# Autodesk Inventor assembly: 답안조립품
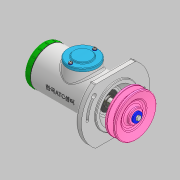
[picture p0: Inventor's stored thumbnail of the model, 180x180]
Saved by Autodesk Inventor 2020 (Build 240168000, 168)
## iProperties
Created: 2022-05
Part Number: 답안조립품
Document SubType Name: Assembly
Designer: User
Author: User
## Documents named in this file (22)
- C:\Users\User\Desktop\720506V1035\답안조립품.iam
- C:\Users\User\Desktop\720506V1035\본체.ipt
- C:\Users\User\Desktop\720506V1035\V-벨트풀리.ipt
- C:\Users\User\Desktop\720506V1035\개스킷.ipt
- C:\Users\User\Desktop\720506V1035\너트 M10.ipt
- C:\Users\User\Desktop\720506V1035\멈춤나사 M3.ipt
- C:\Users\User\Desktop\720506V1035\멈춤링 15 x 1.ipt
- C:\Users\User\Desktop\720506V1035\멈춤링 35 x 1.6.ipt
- C:\Users\User\Desktop\720506V1035\베어링 6202.ipt
- C:\Users\User\Desktop\720506V1035\볼트 M4 x 10.ipt
- C:\Users\User\Desktop\720506V1035\부시1.ipt
- C:\Users\User\Desktop\720506V1035\부시2.ipt
- C:\Users\User\Desktop\720506V1035\사이드 커버.ipt
- 사이드 커버.ipt
- C:\Users\User\Desktop\720506V1035\십자볼트 M3 x 10.ipt
- C:\Users\User\Desktop\720506V1035\오일 실 15 x 30 x 7.ipt
- C:\Users\User\Desktop\720506V1035\와셔 3 x 6.ipt
- C:\Users\User\Desktop\720506V1035\와셔 4 x 16.ipt
- C:\Users\User\Desktop\720506V1035\와셔 10 x 21.ipt
- C:\Users\User\Desktop\720506V1035\축.ipt
- C:\Users\User\Desktop\720506V1035\키 4 x 4.ipt
- C:\Users\User\Desktop\720506V1035\탑 커버.ipt
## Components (3 placed, 3 different names)
1. V-벨트풀리:1
2. 개스킷:1 — 각도:14
3. ISO 4017 M4 x 10:1 — 각도:15
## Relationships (2: Angle 2)
- 각도:14 [Angle]: 개스킷:1
- 각도:15 [Angle]: ISO 4017 M4 x 10:1
